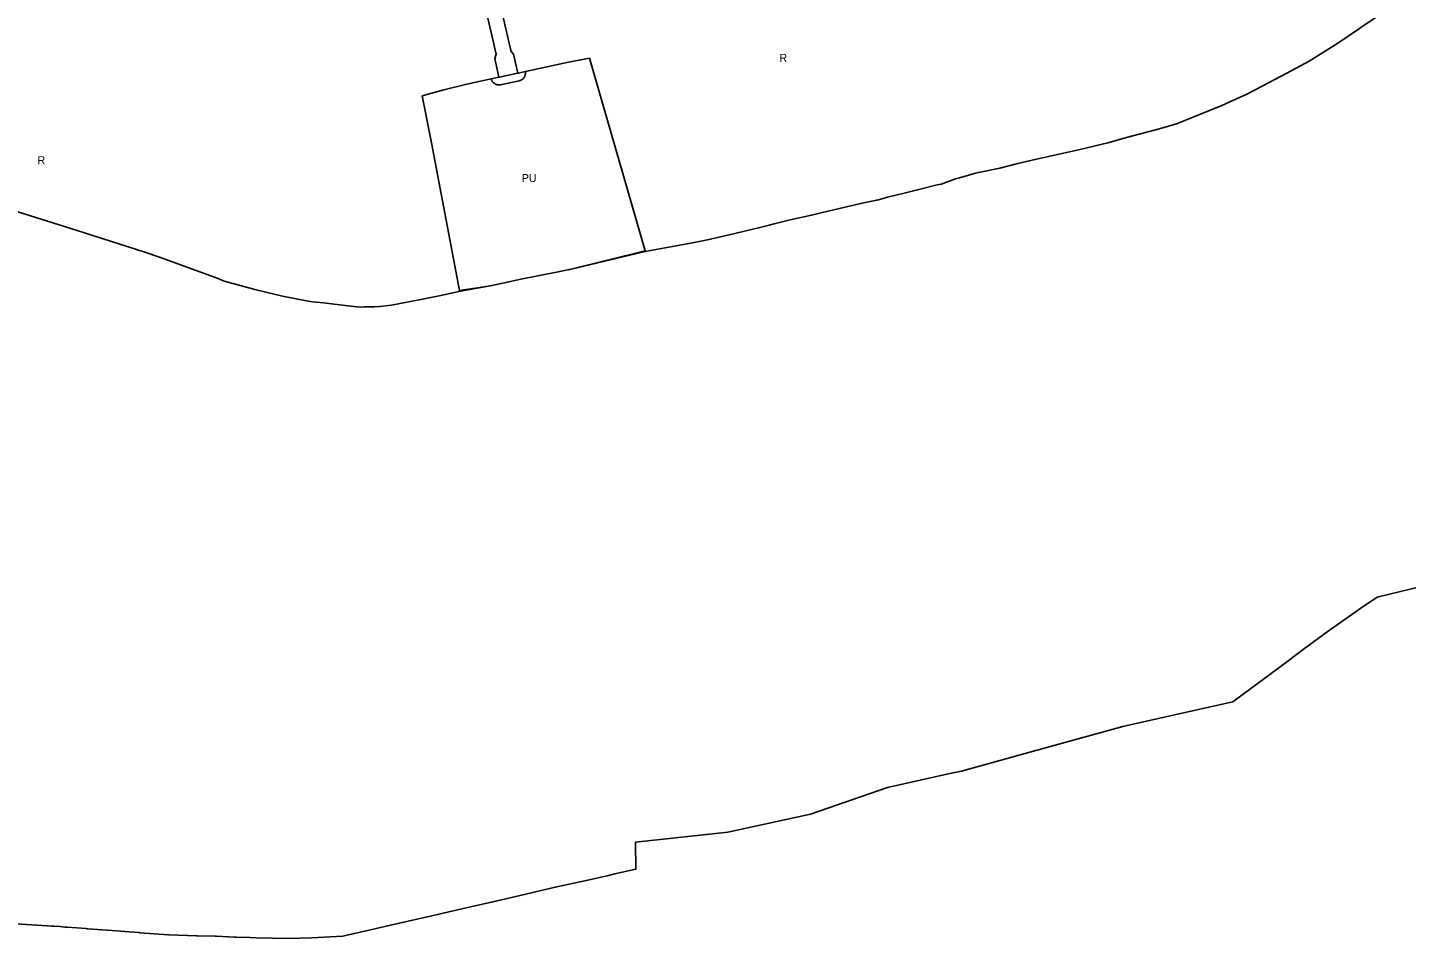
# Model space of a CAD drawing. Extents: x 7435758 to 7439981, y 5550649 to 5554049.
# Drawn here: x 7436617 to 7437513, y 5550649 to 5551241 of the extents above; entities that cross this region are included whole.
import ezdxf

# ---------------------------------------------------------------- set-up
doc = ezdxf.new("R2010")
doc.units = 0
for name, color, linetype in [('#Ruszcza', 7, 'Continuous'), ('linie_rozgraniczające', 7, 'Continuous'), ('linie_zabudowy_nieprzekraczalne', 7, 'Continuous'), ('oznaczenia_przeznaczen', 7, 'Continuous')]:
    doc.layers.add(name, color=color, linetype=linetype)

msp = doc.modelspace()

# ---------------------------------------------------------------- linework, layer by layer
at = {"layer": '#Ruszcza'}
for p, q in [((7436690.26, 5550653.12), (7436709.05, 5550651.72)), ((7436765.92, 5550649.81), (7436765.92, 5550649.81)), ((7436765.92, 5550649.81), (7436765.92, 5550649.81))]:
    msp.add_line(p, q, dxfattribs=at)
for points in [[(7437498.58, 5551251.32), (7437483.4, 5551241.05), (7437482.57, 5551240.49), (7437467.84, 5551230.6), (7437449.84, 5551219.18), (7437435.5, 5551211.43), (7437419.78, 5551203.19), (7437409.48, 5551197.81), (7437405.17, 5551195.88), (7437393.16, 5551190.48), (7437385.26, 5551187.16), (7437375.1, 5551183.07), (7437364.41, 5551178.76), (7437356.36, 5551176.49), (7437347.84, 5551173.98), (7437331.32, 5551169.74), (7437327.65, 5551168.67), (7437319.25, 5551166.14), (7437300.14, 5551161.71), (7437272.72, 5551155.54), (7437260.59, 5551152.8), (7437249.11, 5551149.86), (7437235.13, 5551146.96), (7437233.19, 5551146.52), (7437222.74, 5551143.58), (7437220.21, 5551142.76), (7437210.95, 5551139.45), (7437208.34, 5551138.83), (7437196.36, 5551135.82), (7437186.76, 5551133.45), (7437176.11, 5551130.84), (7437173.2, 5551130.13), (7437169.04, 5551128.98), (7437161.58, 5551127.42), (7437149.31, 5551124.55), (7437124.69, 5551118.86), (7437112.72, 5551116.14), (7437102.35, 5551113.55), (7437099.1, 5551112.69), (7437092.32, 5551110.93), (7437073.26, 5551106.55), (7437059.07, 5551103.28), (7437054.7, 5551102.3), (7437045.9, 5551100.65), (7437038.68, 5551099.31), (7437019.75, 5551095.82), (7437018.7, 5551095.56), (7436994.1, 5551089.68), (7436993.29, 5551089.49), (7436973.25, 5551084.69), (7436963.1, 5551082.67), (7436936.86, 5551077.42), (7436929.09, 5551075.73), (7436917.98, 5551073.31), (7436898.58, 5551069.8), (7436884.88, 5551066.87), (7436874.03, 5551064.64), (7436853.76, 5551060.82), (7436846.36, 5551059.8), (7436842.39, 5551059.7), (7436835.89, 5551059.59), (7436833.52, 5551059.5), (7436827.44, 5551060.18), (7436814.89, 5551061.63), (7436809.59, 5551062.22), (7436802.43, 5551063.02), (7436799.71, 5551063.33), (7436783.03, 5551066.66), (7436765.93, 5551070.83), (7436745.23, 5551076.44), (7436740.57, 5551078.23), (7436703.8, 5551091.77), (7436692.89, 5551095.34), (7436682.04, 5551098.88), (7436649.61, 5551109.17), (7436611.08, 5551121.48)], [(7436765.92, 5550649.81), (7436765.93, 5550649.81), (7436787.23, 5550649.42), (7436801.97, 5550649.86), (7436822.3, 5550650.94), (7436840.19, 5550654.99), (7436853.13, 5550657.96), (7436880.99, 5550664.38), (7436899.53, 5550668.59), (7436919.6, 5550673.24), (7436937.4, 5550677.32), (7436960.14, 5550682.66), (7436981.27, 5550687.24), (7436994.79, 5550690.4), (7436998.96, 5550691.37), (7437012.6, 5550694.43), (7437012.36, 5550711.98), (7437072.37, 5550718.54), (7437126.08, 5550730.18), (7437175.95, 5550747.44), (7437218.57, 5550756.93), (7437224.12, 5550758.17), (7437268.42, 5550770.49), (7437328.86, 5550787.12), (7437350.91, 5550792.05), (7437390.61, 5550800.84), (7437400.33, 5550803), (7437401.3, 5550803.68), (7437431.05, 5550825.84), (7437447, 5550837.74), (7437462.36, 5550849.06), (7437483.52, 5550863.97), (7437494.09, 5550871.19), (7437508.31, 5550874.47), (7437524.48, 5550878.48)], [(7436597.84, 5550659.64), (7436597.84, 5550659.64), (7436599.2, 5550659.58), (7436599.21, 5550659.58), (7436623.56, 5550658.05), (7436633.12, 5550657.46), (7436634.57, 5550657.36)], [(7436634.57, 5550657.36), (7436634.57, 5550657.36), (7436638.55, 5550657.13), (7436641.56, 5550656.83)], [(7436641.56, 5550656.83), (7436641.57, 5550656.83), (7436643.09, 5550656.7), (7436655.54, 5550655.77), (7436655.77, 5550655.75)], [(7436655.77, 5550655.75), (7436656.47, 5550655.73), (7436675.13, 5550654.28), (7436675.13, 5550654.28)], [(7436675.13, 5550654.28), (7436683.19, 5550653.66), (7436683.2, 5550653.66)], [(7436683.2, 5550653.66), (7436689.81, 5550653.17), (7436690.26, 5550653.12)], [(7436709.05, 5550651.72), (7436709.51, 5550651.72), (7436727.26, 5550651.13), (7436727.79, 5550651.1), (7436739.29, 5550650.87), (7436739.32, 5550650.87)], [(7436739.32, 5550650.87), (7436740.02, 5550650.86), (7436740.21, 5550650.85)], [(7436740.21, 5550650.85), (7436740.21, 5550650.85), (7436751.79, 5550650.3), (7436753.08, 5550650.25), (7436762.02, 5550650), (7436765.92, 5550649.81)]]:
    msp.add_lwpolyline(points, dxfattribs=at)
at = {"layer": 'linie_rozgraniczające'}
for p, q in [((7436931.05, 5551227.33), (7436923.53, 5551259.89)), ((7436914.38, 5551255.61), (7436921.72, 5551223.76)), ((7436921.72, 5551223.76), (7436920.85, 5551220.99)), ((7436931.29, 5551226.25), (7436931.05, 5551227.33)), ((7436931.48, 5551225.45), (7436931.29, 5551226.25)), ((7436933.05, 5551223.72), (7436931.48, 5551225.45)), ((7436935.81, 5551211.44), (7436933.05, 5551223.72)), ((7436920.85, 5551220.99), (7436923.56, 5551208.82)), ((7436967.82, 5551218.31), (7436938.84, 5551212.09)), ((7436982.44, 5551221.26), (7436967.82, 5551218.31)), ((7437018.71, 5551095.99), (7436982.44, 5551221.26)), ((7436901.89, 5551204.18), (7436887.77, 5551200.6)), ((7436904.82, 5551204.81), (7436901.89, 5551204.18)), ((7436923.56, 5551208.82), (7436904.82, 5551204.81)), ((7436923.56, 5551208.82), (7436923.98, 5551208.91)), ((7436923.98, 5551208.91), (7436925.08, 5551209.15)), ((7436925.08, 5551209.15), (7436926.84, 5551209.52)), ((7436926.84, 5551209.52), (7436934.77, 5551211.22)), ((7436934.77, 5551211.22), (7436935.81, 5551211.44)), ((7436936.37, 5551211.56), (7436935.81, 5551211.44)), ((7436938.84, 5551212.09), (7436936.37, 5551211.56)), ((7436887.77, 5551200.6), (7436873.73, 5551196.68)), ((7436873.73, 5551196.68), (7436879.85, 5551166.15)), ((7436879.85, 5551166.15), (7436898.01, 5551070.33)), ((7436968.79, 5551083.8), (7437018.71, 5551095.99)), ((7436898.01, 5551070.33), (7436913.92, 5551072.58))]:
    msp.add_line(p, q, dxfattribs=at)
msp.add_lwpolyline([(7437498.58, 5551251.32), (7437483.4, 5551241.05), (7437482.57, 5551240.49), (7437467.84, 5551230.6), (7437449.84, 5551219.18), (7437435.5, 5551211.43), (7437419.78, 5551203.19), (7437409.48, 5551197.81), (7437405.17, 5551195.88), (7437393.16, 5551190.48), (7437385.26, 5551187.16), (7437375.1, 5551183.07), (7437364.41, 5551178.76), (7437356.36, 5551176.49), (7437347.84, 5551173.98), (7437331.32, 5551169.74), (7437327.65, 5551168.67), (7437319.25, 5551166.14), (7437300.14, 5551161.71), (7437272.72, 5551155.54), (7437260.59, 5551152.8), (7437249.11, 5551149.86), (7437235.13, 5551146.96), (7437233.19, 5551146.52), (7437222.74, 5551143.58), (7437220.21, 5551142.76), (7437210.95, 5551139.45), (7437208.34, 5551138.83), (7437196.36, 5551135.82), (7437186.76, 5551133.45), (7437176.11, 5551130.84), (7437173.2, 5551130.13), (7437169.04, 5551128.98), (7437161.58, 5551127.42), (7437149.31, 5551124.55), (7437124.69, 5551118.86), (7437112.72, 5551116.14), (7437102.35, 5551113.55), (7437099.1, 5551112.69), (7437092.32, 5551110.93), (7437073.26, 5551106.55), (7437059.07, 5551103.28), (7437054.7, 5551102.3), (7437045.9, 5551100.65), (7437038.68, 5551099.31), (7437019.75, 5551095.82), (7437018.7, 5551095.56), (7436994.1, 5551089.68), (7436993.29, 5551089.49), (7436973.25, 5551084.69), (7436963.1, 5551082.67), (7436936.86, 5551077.42), (7436929.09, 5551075.73), (7436917.98, 5551073.31), (7436898.58, 5551069.8), (7436884.88, 5551066.87), (7436874.03, 5551064.64), (7436853.76, 5551060.82), (7436846.36, 5551059.8), (7436842.39, 5551059.7), (7436835.89, 5551059.59), (7436833.52, 5551059.5), (7436827.44, 5551060.18), (7436814.89, 5551061.63), (7436809.59, 5551062.22), (7436802.43, 5551063.02), (7436799.71, 5551063.33), (7436783.03, 5551066.66), (7436765.93, 5551070.83), (7436745.23, 5551076.44), (7436740.57, 5551078.23), (7436703.8, 5551091.77), (7436692.89, 5551095.34), (7436682.04, 5551098.88), (7436649.61, 5551109.17), (7436611.08, 5551121.48)], dxfattribs=at)
at = {"layer": 'linie_zabudowy_nieprzekraczalne'}
msp.add_lwpolyline([(7436940.7, 5551212.46), (7436940.74, 5551212.3), (7436940.78, 5551211.97), (7436940.81, 5551211.65), (7436940.81, 5551211.32), (7436940.79, 5551210.99), (7436940.75, 5551210.67), (7436940.69, 5551210.35), (7436940.61, 5551210.03), (7436940.5, 5551209.72), (7436940.38, 5551209.42), (7436940.24, 5551209.12), (7436940.08, 5551208.84), (7436939.9, 5551208.56), (7436939.7, 5551208.3), (7436939.49, 5551208.05), (7436939.26, 5551207.82), (7436939.01, 5551207.6), (7436938.75, 5551207.4), (7436938.48, 5551207.22), (7436938.2, 5551207.05), (7436937.91, 5551206.91), (7436937.61, 5551206.78), (7436937.3, 5551206.67), (7436936.98, 5551206.58), (7436936.86, 5551206.55), (7436924.61, 5551203.93), (7436924.41, 5551203.89), (7436924.09, 5551203.85), (7436923.76, 5551203.82), (7436923.43, 5551203.82), (7436923.11, 5551203.84), (7436922.78, 5551203.88), (7436922.46, 5551203.94), (7436922.14, 5551204.02), (7436921.83, 5551204.13), (7436921.53, 5551204.25), (7436921.24, 5551204.39), (7436920.95, 5551204.55), (7436920.68, 5551204.73), (7436920.42, 5551204.93), (7436920.17, 5551205.14), (7436919.94, 5551205.37), (7436919.72, 5551205.62), (7436919.52, 5551205.88), (7436919.33, 5551206.15), (7436919.17, 5551206.43), (7436919.02, 5551206.72), (7436918.89, 5551207.02), (7436918.79, 5551207.33), (7436918.7, 5551207.65), (7436918.68, 5551207.73), (7436918.67, 5551207.78)], dxfattribs=at)

# ---------------------------------------------------------------- texts
at = {"layer": 'oznaczenia_przeznaczen'}
for s, p in [('R', (7437105.75, 5551218.81)), ('R', (7436623.88, 5551152.32)), ('PU', (7436938.46, 5551140.73))]:
    msp.add_text(s, height=5.2, dxfattribs=at).set_placement(p)

doc.saveas('drawing.dxf')
